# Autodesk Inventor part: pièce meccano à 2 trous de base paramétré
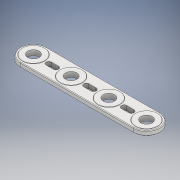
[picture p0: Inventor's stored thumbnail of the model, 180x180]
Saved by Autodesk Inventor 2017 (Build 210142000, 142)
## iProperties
Part Number: pièce meccano à 2 trous de base paramétré
Material: Plastique PC/ABS
Document SubType Name: Modeling
Designer: ficho
Density: 0.357273 g/cm^3
Appearance: Lisse - Blanc
Author: ficho
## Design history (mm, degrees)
sketch "Esquisse1"
  geometry: L1 (94.5, 11)-(0, 11); L2 (94.5, -11)-(0, -11); A1 r 11 centre (0, 0) between (0, 11) and (0, -11); A2 r 11 centre (94.5, 0) between (94.5, -11) and (94.5, 11); 1 further point
  constraints: 4 end point, 4 point on circle, 4 tangent, 2 centre point, 1 coincident
  dimensions: "d0" = 22 diameter of A1 (= largeur); "d1" = 22 diameter of A2 (= largeur); "d2" = 116.5 dimension on A2 A1 (= long)
extrude "Extrusion1" new body sketch "Esquisse1" distance "d3" = 3.8 (= ep); taper "d4" = 0 deg
fillet "Congé1" dims "d5" = 0.5
fillet "Congé2" dims "d6" = 0.5
sketch "Esquisse2"
  geometry: C1 r 9.15 at (0, 0); 1 further point
  constraints: 1 centre point, 1 coincident
  dimensions: "d14" = 18.3 diameter of C1
extrude "Extrusion2" join sketch "Esquisse2" distance "d15" = 0.25; taper "d16" = 0 deg
node "Plan de construction1"
mirror "Symétrie1"
fillet "Congé4" dims "d19" = 0.25
sketch "Esquisse4"
  geometry: 1 further point
hole "Perçage2" sketch "Esquisse4" at (0, 0) diameter "d20" = 9.5 (= alesage); stored, may be unused: countersink angle "d24" = 90 deg, drill point angle "d26" = 118 deg; dims "d21" = 6, "d22" = 4, "d23" = 2, "d25" = 8
pattern_linear "Réseau rectangulaire1" dims "d29" = 31.5 (= repet)
sketch "Esquisse5"
  geometry: L1 (18.75, 2)-(12.75, 2); L2 (18.75, -2)-(12.75, -2); C1 r 4.75 at (31.5, 0) reference; A1 r 2 centre (18.75, 0) between (18.75, -2) and (18.75, 2); A2 r 2 centre (12.75, 0) between (12.75, 2) and (12.75, -2); 1 further point
  constraints: 4 end point, 4 point on circle, 4 tangent, 2 centre point
  dimensions: "d30" = 4 diameter of A1; "d31" = 4 diameter of A2; "d32" = 6 distance of A2.centre A1.centre; "d33" = 12.75 distance of A2.centre point (0, 0)
extrude "Extrusion3" cut sketch "Esquisse5" stored distance "d35" = 0.25; taper "d36" = 0 deg
fillet "Congé5" dims "d37" = 0.25
pattern_linear "Réseau rectangulaire2" dims "d40" = 31.5 (= repet)
node "Solide1"
other parameters: "largeur" = 22 [user parameter; used in 2 equation terms], "long" = 116.5 [user parameter; used in 1 equation term], "ep" = 3.8 [user parameter; used in 2 equation terms], "alesage" = 9.5 [user parameter; used in 1 equation term], "d18" = -1.9 (= -0.5 x ep), "repet" = 31.5 [user parameter; used in 2 equation terms]
